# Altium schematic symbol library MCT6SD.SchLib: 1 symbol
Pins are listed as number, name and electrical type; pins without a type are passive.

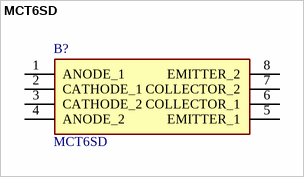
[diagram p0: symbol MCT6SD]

## MCT6SD
designator B?
Choice of 3 current transfer ratios; Two isolated channels per package; VDE approved for IEC60747-5-2; Two packages fit into a 16 lead DIP socket; Underwriters Laboratory (U.L.) recognized File E90700; Manufacturer_Name: onsemi; Geometry.Height: 3.85mm
footprint SOP254P1016X385-8N
pins: 1 ANODE_1, 2 CATHODE_1, 3 CATHODE_2, 4 ANODE_2, 5 EMITTER_1, 6 COLLECTOR_1, 7 COLLECTOR_2, 8 EMITTER_2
